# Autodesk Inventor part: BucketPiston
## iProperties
Author: vincent molino
Shininess: 86.0
Angle Display Precision: 2
Document Length Units: 11272
Document Angle Units: 11286
Document Time Units: 11279
Document Mass Units: 11290
Document Length Units Precision: 3
Document Angle Units Precision: 2
Compacted: True
PropertySet Name: _Private Model Information
Created: 2002-01
Part Number: BucketPiston
Document SubType Name: Modeling
Designer: vincent molino
Control State: 0
Master: False
Checked Out: False
PropertySet Name: Design Tracking Control
Density: 0.0
Volumn: 0.0
Area: 0.0
PropertySet Name: Model Information
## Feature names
1. Extrusion1
2. Extrusion2
3. Extrusion3
